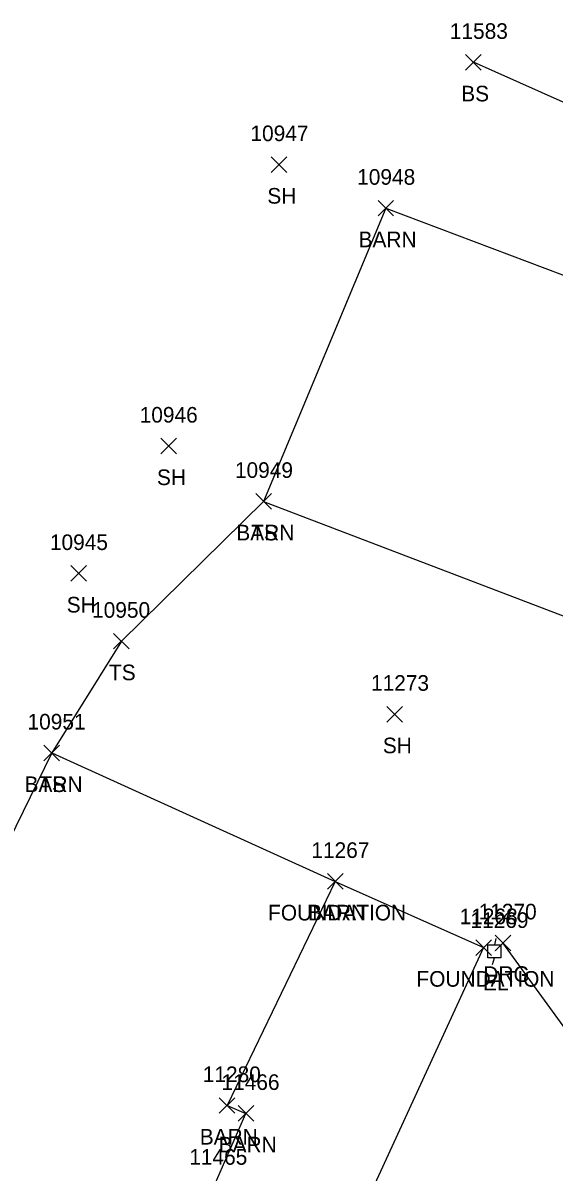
# Model space of a CAD drawing. Extents: x 1475671 to 1477951, y 592661 to 593821.
# Drawn here: x 1476763.3 to 1476831.3, y 593424.9 to 593572.2 of the extents above; entities that cross this region are included whole.
import ezdxf

# ---------------------------------------------------------------- set-up
doc = ezdxf.new("R2010")
doc.units = 0
for name, color, linetype in [('L_A', 7, 'Continuous'), ('L_I', 7, 'Continuous'), ('L_TIC', 7, 'Continuous'), ('LBC', 7, 'Continuous'), ('LELB', 7, 'Continuous'), ('R_A', 7, 'Continuous'), ('R_I', 7, 'Continuous'), ('R_TIC', 7, 'Continuous'), ('RDG', 7, 'Continuous'), ('U_A', 7, 'Continuous'), ('U_I', 7, 'Continuous'), ('UEPT', 7, 'Continuous')]:
    doc.layers.add(name, color=color, linetype=linetype)

msp = doc.modelspace()

# ---------------------------------------------------------------- linework, layer by layer
at = {"layer": 'L_TIC'}
for points in [[(1476820.01, 593566.13), (1476822.01, 593568.13)], [(1476822.01, 593566.13), (1476820.01, 593568.13)], [(1476795.12, 593553.04), (1476797.12, 593555.04)], [(1476797.12, 593553.04), (1476795.12, 593555.04)], [(1476808.79, 593547.46), (1476810.79, 593549.46)], [(1476810.79, 593547.46), (1476808.79, 593549.46)], [(1476808.79, 593547.46), (1476810.79, 593549.46)], [(1476810.79, 593547.46), (1476808.79, 593549.46)], [(1476780.98, 593517.01), (1476782.98, 593519.01)], [(1476782.98, 593517.01), (1476780.98, 593519.01)], [(1476793.13, 593509.93), (1476795.13, 593511.93)], [(1476795.13, 593509.93), (1476793.13, 593511.93)], [(1476793.13, 593509.93), (1476795.13, 593511.93)], [(1476795.13, 593509.93), (1476793.13, 593511.93)], [(1476769.43, 593500.7), (1476771.43, 593502.7)], [(1476771.43, 593500.7), (1476769.43, 593502.7)], [(1476774.92, 593492.03), (1476776.92, 593494.03)], [(1476776.92, 593492.03), (1476774.92, 593494.03)], [(1476809.92, 593482.68), (1476811.92, 593484.68)], [(1476811.92, 593482.68), (1476809.92, 593484.68)], [(1476765.99, 593477.72), (1476767.99, 593479.72)], [(1476767.99, 593477.72), (1476765.99, 593479.72)], [(1476765.99, 593477.72), (1476767.99, 593479.72)], [(1476767.99, 593477.72), (1476765.99, 593479.72)], [(1476765.99, 593477.72), (1476767.99, 593479.72)], [(1476767.99, 593477.72), (1476765.99, 593479.72)], [(1476802.32, 593461.28), (1476804.32, 593463.28)], [(1476804.32, 593461.28), (1476802.32, 593463.28)], [(1476802.32, 593461.28), (1476804.32, 593463.28)], [(1476804.32, 593461.28), (1476802.32, 593463.28)], [(1476821.31, 593452.8), (1476823.31, 593454.8)], [(1476823.31, 593452.8), (1476821.31, 593454.8)], [(1476788.45, 593432.59), (1476790.45, 593434.59)], [(1476790.45, 593432.59), (1476788.45, 593434.59)], [(1476790.87, 593431.58), (1476792.87, 593433.58)], [(1476792.87, 593431.58), (1476790.87, 593433.58)], [(1476790.87, 593431.58), (1476792.87, 593433.58)], [(1476792.87, 593431.58), (1476790.87, 593433.58)]]:
    msp.add_lwpolyline(points, dxfattribs=at)
at = {"layer": 'LBC'}
for points in [[(1476809.79, 593548.46), (1476794.13, 593510.93), (1476851.32, 593489.12), (1476844.55, 593472.48), (1476848.98, 593470.67), (1476861.45, 593465.84), (1476868.26, 593482.59), (1476889.17, 593474.66), (1476903.53, 593512.02), (1476877.63, 593522.41), (1476851.06, 593532.69), (1476834.7, 593539.09)], [(1476809.79, 593548.46), (1476834.7, 593539.09)], [(1476766.99, 593478.72), (1476749.47, 593442.92), (1476737.05, 593415.38), (1476717.88, 593373.12), (1476703.46, 593340.35), (1476741.92, 593322.87), (1476753.1, 593346.5), (1476762.35, 593367.35), (1476787.68, 593423.01), (1476791.87, 593432.58)], [(1476766.99, 593478.72), (1476803.32, 593462.28), (1476789.45, 593433.59), (1476791.87, 593432.58)], [(1476803.32, 593462.28), (1476822.31, 593453.8), (1476804.46, 593415.03), (1476787.68, 593423.01)]]:
    msp.add_lwpolyline(points, dxfattribs=at)
at = {"layer": 'LELB'}
for points in [[(1476834.7, 593539.09), (1476835.65, 593560.61), (1476821.01, 593567.13)], [(1476794.13, 593510.93), (1476775.92, 593493.03), (1476766.99, 593478.72)]]:
    msp.add_lwpolyline(points, dxfattribs=at)
at = {"layer": 'R_TIC'}
for points in [[(1476823.79, 593453.41), (1476825.79, 593455.41)], [(1476825.79, 593453.41), (1476823.79, 593455.41)]]:
    msp.add_lwpolyline(points, dxfattribs=at)
at = {"layer": 'RDG'}
msp.add_lwpolyline([(1476799.68, 593374.04), (1476811.74, 593388.84), (1476829.61, 593411.11), (1476841.26, 593431.75), (1476824.79, 593454.41)], dxfattribs=at)
at = {"layer": 'UEPT'}
for p, q in [((1476822.87, 593452.49), (1476822.87, 593454.16)), ((1476822.87, 593454.16), (1476824.54, 593454.16)), ((1476823.87, 593454.99), (1476823.71, 593454.16)), ((1476824.54, 593454.16), (1476824.54, 593452.49)), ((1476824.54, 593452.49), (1476822.87, 593452.49)), ((1476823.46, 593451.66), (1476823.71, 593452.49)), ((1476823.71, 593453.32), (1476823.71, 593453.32))]:
    msp.add_line(p, q, dxfattribs=at)

# ---------------------------------------------------------------- texts
at = {"layer": 'L_A'}
for s, p in [('BS', (1476819.45, 593562.13)), ('SH', (1476794.61, 593549.04)), ('BARN', (1476806.3, 593543.46)), ('BARN', (1476806.3, 593543.46)), ('SH', (1476780.47, 593513.01)), ('BARN', (1476790.64, 593505.93)), ('TS', (1476792.54, 593505.93)), ('SH', (1476768.91, 593496.7)), ('TS', (1476774.33, 593488.03)), ('SH', (1476809.41, 593478.68)), ('BARN', (1476763.51, 593473.72)), ('BARN', (1476763.51, 593473.72)), ('TS', (1476765.4, 593473.72)), ('FOUNDATION', (1476794.71, 593457.28)), ('BARN', (1476799.83, 593457.28)), ('FOUNDATION', (1476813.71, 593448.8)), ('BARN', (1476785.96, 593428.59)), ('BARN', (1476788.38, 593427.58)), ('BARN', (1476788.38, 593427.58))]:
    msp.add_text(s, height=2, dxfattribs=at).set_placement(p)
at = {"layer": 'L_I'}
for s, p in [('11583', (1476817.99, 593570.13)), ('10947', (1476792.45, 593557.04)), ('10948', (1476806.12, 593551.46)), ('10948', (1476806.12, 593551.46)), ('10946', (1476778.26, 593521.01)), ('10949', (1476790.46, 593513.93)), ('10949', (1476790.46, 593513.93)), ('10945', (1476766.76, 593504.7)), ('10950', (1476772.16, 593496.03)), ('11273', (1476807.89, 593486.68)), ('10951', (1476763.89, 593481.72)), ('10951', (1476763.89, 593481.72)), ('10951', (1476763.89, 593481.72)), ('11267', (1476800.25, 593465.28)), ('11267', (1476800.25, 593465.28)), ('11268', (1476819.24, 593456.8)), ('11280', (1476786.34, 593436.59)), ('11466', (1476788.74, 593435.58)), ('11466', (1476788.74, 593435.58)), ('11465', (1476784.61, 593426.01)), ('11465', (1476784.61, 593426.01))]:
    msp.add_text(s, height=2, dxfattribs=at).set_placement(p)
at = {"layer": 'R_A'}
msp.add_text('DRG', height=2, dxfattribs=at).set_placement((1476822.28, 593449.41))
at = {"layer": 'R_I'}
msp.add_text('11270', height=2, dxfattribs=at).set_placement((1476821.68, 593457.41))
at = {"layer": 'U_A'}
msp.add_text('EL', height=2, dxfattribs=at).set_placement((1476822.24, 593448.32))
at = {"layer": 'U_I'}
msp.add_text('11269', height=2, dxfattribs=at).set_placement((1476820.63, 593456.32))

doc.saveas('drawing.dxf')
